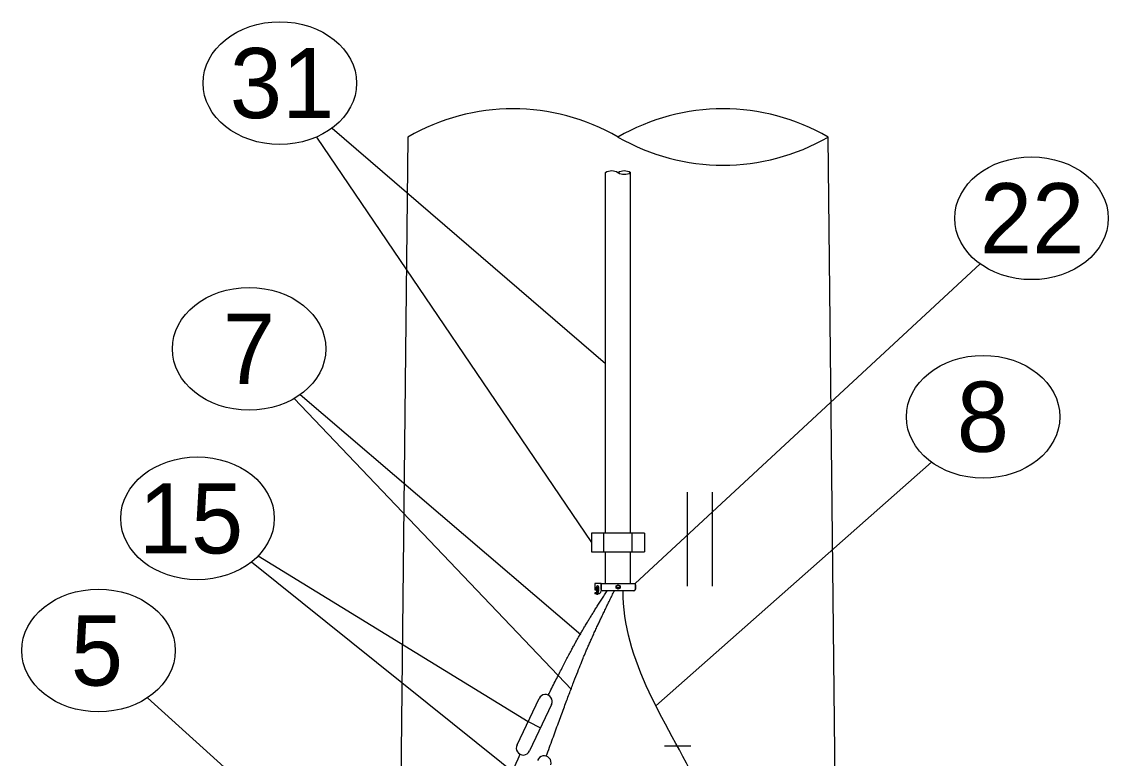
# Model space of a CAD drawing. Extents: x 99862 to 104211, y 98939 to 102076.
# Drawn here: x 101734.6 to 101982.3, y 101365.3 to 101533.3 of the extents above; entities that cross this region are included whole.
import ezdxf

# ---------------------------------------------------------------- set-up
doc = ezdxf.new("R2010")
doc.units = 0
for name, color, linetype in [('Level 1', 7, 'Continuous'), ('Level 11', 7, 'Continuous'), ('Level 15', 7, 'Continuous'), ('Level 17', 7, 'Continuous'), ('Level 20', 7, 'Continuous'), ('Level 7', 7, 'Continuous'), ('Level 8', 7, 'Continuous'), ('Level 9', 7, 'Continuous')]:
    doc.layers.add(name, color=color, linetype=linetype)

msp = doc.modelspace()

# ---------------------------------------------------------------- linework, layer by layer
at = {"layer": 'Level 1'}
for p, q in [((101822.66, 101507.01), (101818.5, 101124.11)), ((101922.64, 101123.74), (101918.48, 101507.01))]:
    msp.add_line(p, q, dxfattribs=at)
for centre, start, end in [((101846.62, 101465.52), 60, 120), ((101894.52, 101465.52), 60, 120), ((101894.52, 101548.5), 240, 300)]:
    msp.add_arc(centre, 47.91, start, end, dxfattribs=at)
at = {"layer": 'Level 11'}
for p, q in [((101865.95, 101403.14), (101865.96, 101403.07)), ((101881.2, 101368.11), (101887.2, 101368.11))]:
    msp.add_line(p, q, dxfattribs=at)
for points, degree in [([(101854.22, 101365.79), (101860.66, 101383.54), (101865.31, 101394.5), (101869.75, 101403.52)], 2), ([(101854.67, 101379.69), (101859.16, 101388.63), (101863.75, 101396.77), (101868.08, 101403.52)], 2), ([(101880.31, 101302.54), (101883.77, 101302.51), (101890.12, 101302.55), (101894.49, 101320.44), (101899.51, 101330.05), (101891.01, 101357.11), (101876.44, 101380.43), (101871.67, 101395.71), (101871.77, 101403.52)], 3), ([(101850, 101257.11), (101811.89, 101257.11), (101826.6, 101318.15), (101848.24, 101366.2)], 2)]:
    msp.add_open_spline(points, degree=degree, dxfattribs=at)
at = {"layer": 'Level 15'}
for p, q in [((101805.37, 101509.05), (101867.72, 101455.33)), ((101801.8, 101507.01), (101864.51, 101414.5)), ((101953.11, 101478.1), (101874.45, 101405.15)), ((101796.73, 101447.36), (101859.93, 101380.97)), ((101798.13, 101448.27), (101862.07, 101393.55)), ((101942.08, 101432.82), (101879.19, 101377.25)), ((101788.56, 101411.49), (101850.06, 101373.65)), ((101787.04, 101410.1), (101850.38, 101359.23)), ((101763.3, 101379.1), (101791.07, 101353.99))]:
    msp.add_line(p, q, dxfattribs=at)
at = {"layer": 'Level 17'}
for p, q in [((101847.56, 101368.36), (101852.57, 101378.94)), ((101855.42, 101377.59), (101850.38, 101366.95)), ((101850.06, 101373.65), (101852.9, 101372.27))]:
    msp.add_line(p, q, dxfattribs=at)
for centre, start, end in [((101853.99, 101378.27), 334.6567, 154.6863), ((101848.95, 101367.61), 151.5959, 335.2767), ((101853.73, 101364.29), 341.6062, 161.6358)]:
    msp.add_arc(centre, 1.58, start, end, dxfattribs=at)
at = {"layer": 'Level 20'}
for centre in [(101793.46, 101519.31), (101964.85, 101488.47), (101786.46, 101458.7), (101953.82, 101443.2), (101774.69, 101420.02), (101752.12, 101389.87)]:
    msp.add_ellipse(centre, major_axis=(-17.5, 0), ratio=0.8, dxfattribs=at)
at = {"layer": 'Level 7'}
for p, q in [((101886.35, 101425.97), (101886.35, 101404.53)), ((101892.06, 101425.97), (101892.06, 101404.53))]:
    msp.add_line(p, q, dxfattribs=at)
for points in [[(101866.73, 101403.78), (101866.73, 101405.15), (101874.45, 101405.15), (101874.45, 101403.78)], [(101874.19, 101403.52), (101866.99, 101403.52)]]:
    msp.add_lwpolyline(points, dxfattribs=at)
for centre, start, end in [((101866.99, 101403.78), 180, 270), ((101874.19, 101403.78), 270, 0)]:
    msp.add_arc(centre, 0.263, start, end, dxfattribs=at)
at = {"layer": 'Level 8'}
for p, q in [((101867.72, 101416.64), (101867.72, 101498.88)), ((101873.42, 101416.64), (101873.42, 101498.88)), ((101864.51, 101416.64), (101864.51, 101412.36)), ((101876.63, 101416.64), (101864.51, 101416.64)), ((101867.36, 101412.34), (101867.36, 101416.62)), ((101873.78, 101412.34), (101873.78, 101416.62)), ((101876.63, 101416.64), (101876.63, 101412.36)), ((101864.51, 101412.36), (101876.63, 101412.36)), ((101867.72, 101405.15), (101867.72, 101412.36)), ((101873.42, 101405.15), (101873.42, 101412.36)), ((101866.73, 101405.15), (101865.32, 101405.15)), ((101865.32, 101405.15), (101865.32, 101403.75)), ((101866.73, 101405.15), (101866.73, 101403.49)), ((101870.15, 101404.6), (101870.59, 101404.86)), ((101870.15, 101404.09), (101870.15, 101404.6)), ((101870.15, 101404.36), (101871.03, 101404.36)), ((101870.15, 101404.31), (101871.03, 101404.31)), ((101870.59, 101403.84), (101870.15, 101404.09)), ((101870.59, 101404.86), (101871.03, 101404.6)), ((101871.03, 101404.09), (101870.59, 101403.84)), ((101871.03, 101404.6), (101871.03, 101404.09)), ((101874.45, 101404.86), (101874.65, 101404.86)), ((101874.45, 101404.6), (101874.65, 101404.6)), ((101874.45, 101404.09), (101874.65, 101404.09)), ((101874.58, 101404.36), (101874.65, 101404.36)), ((101874.58, 101404.31), (101874.58, 101404.36)), ((101874.58, 101404.31), (101874.65, 101404.31)), ((101874.65, 101404.36), (101874.65, 101404.86)), ((101874.65, 101403.84), (101874.65, 101404.31)), ((101865.32, 101403.75), (101865.55, 101403.75)), ((101865.89, 101403.06), (101865.32, 101403.06)), ((101865.32, 101403.06), (101865.32, 101402.79)), ((101866.03, 101402.79), (101865.32, 101402.79)), ((101874.45, 101403.84), (101874.65, 101403.84))]:
    msp.add_line(p, q, dxfattribs=at)
msp.add_circle((101870.59, 101404.35), 0.441, dxfattribs=at)
for centre, radius, start, end in [((101869.14, 101496.41), 2.85, 60, 120), ((101872, 101496.41), 2.85, 60, 120), ((101872, 101501.35), 2.85, 240, 300), ((101866.03, 101403.49), 0.702, 270, 0)]:
    msp.add_arc(centre, radius, start, end, dxfattribs=at)
for centre, major_axis, ratio, end_param in [((101870.57, 101426.31), (2.85, 0), 0.00604, 0.000009), ((101865.89, 101403.85), (0, -0.799), 0.430882, 4.845732)]:
    msp.add_ellipse(centre, major_axis=major_axis, ratio=ratio, start_param=0, end_param=end_param, dxfattribs=at)
at = {"layer": 'Level 9'}
for p, q in [((101865.64, 101404.34), (101865.64, 101403.06)), ((101865.64, 101404.34), (101865.95, 101404.34)), ((101865.95, 101404.34), (101865.95, 101403.07)), ((101865.64, 101403.06), (101865.64, 101402.79)), ((101865.64, 101402.79), (101865.64, 101402.73)), ((101865.64, 101402.73), (101865.95, 101402.73)), ((101865.95, 101403.07), (101865.95, 101402.79)), ((101865.95, 101402.79), (101865.95, 101402.73))]:
    msp.add_line(p, q, dxfattribs=at)
for centre, start_param in [((101865.76, 101404.18), 1.034303), ((101865.76, 101404.04), 1.034303), ((101865.76, 101403.9), 1.034303), ((101865.76, 101403.76), 1.034303), ((101865.76, 101403.62), 1.034303), ((101865.76, 101403.48), 1.034303), ((101865.76, 101403.34), 1.034303), ((101865.76, 101403.19), 1.034303), ((101865.76, 101403.05), 1.034303), ((101865.76, 101402.91), 1.034303), ((101865.76, 101402.77), 1.034303), ((101865.76, 101402.63), 1.089125)]:
    msp.add_ellipse(centre, major_axis=(0.351, -0.043), ratio=0.361775, start_param=start_param, end_param=1.96922, dxfattribs=at)

# ---------------------------------------------------------------- texts
at = {"layer": 'Level 20'}
for s, p in [('31', (101782.07, 101511.32)), ('22', (101953.09, 101480.48)), ('7', (101780.51, 101450.7)), ('8', (101947.81, 101435.2)), ('15', (101761.31, 101412.02)), ('5', (101745.81, 101381.87))]:
    msp.add_text(s, height=16, dxfattribs=at).set_placement(p)

doc.saveas('drawing.dxf')
